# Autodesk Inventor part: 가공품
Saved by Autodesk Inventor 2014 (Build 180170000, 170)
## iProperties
Created: 2025-02
Part Number: 가공품
Material: 일반
Document SubType Name: Modeling
Designer: dg
Density: 1 g/cm^3
Appearance: 기본값
Author: jhkim
Creation Date: 2025-02-05
Sending System: Autodesk Inventor 2025
Preprocessor: ST-DEVELOPER v20
Author: dg
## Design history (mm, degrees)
node "가공품1"
node "솔리드1"
node "기준1"
